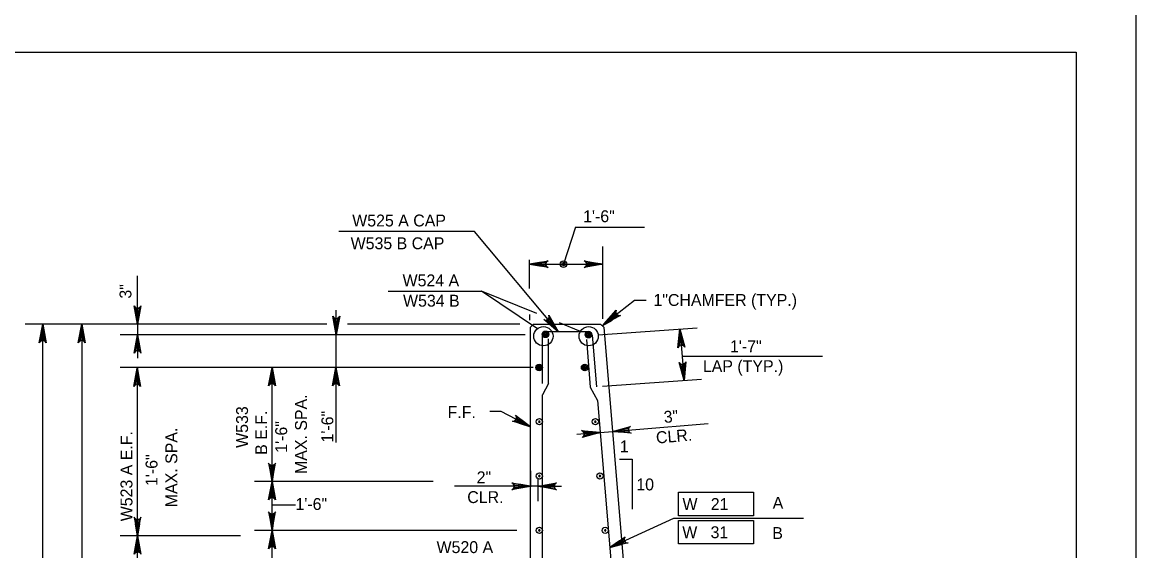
# Model space of a CAD drawing. Extents: x 638255 to 640306, y 296059 to 298435.
# Drawn here: x 639836.8 to 640117.5, y 297700.8 to 297834 of the extents above; entities that cross this region are included whole.
import ezdxf

# ---------------------------------------------------------------- set-up
doc = ezdxf.new("R2010")
doc.units = 0
for name, color, linetype in [('2', 7, 'Continuous'), ('3', 7, 'Continuous'), ('Level 3', 7, 'Continuous'), ('Level 4', 7, 'Continuous'), ('Level 6', 7, 'Continuous'), ('Level 9', 7, 'Continuous'), ('PLT-BNDY', 7, 'Continuous')]:
    doc.layers.add(name, color=color, linetype=linetype)

# ---------------------------------------------------------------- blocks, each defined once
blk = doc.blocks.new('B')
at = {"layer": '3'}
blk.add_circle((0, 0), 0.16, dxfattribs=at)
for start, end in [(0, 180), (180, 0)]:
    blk.add_arc((0, 0), 0.0391, start, end, dxfattribs=at)

msp = doc.modelspace()

# ---------------------------------------------------------------- linework, layer by layer
at = {"layer": '2'}
for p, q in [((639316.46, 297826.46), (640102.46, 297826.46)), ((640102.46, 297826.46), (640102.46, 297262.46))]:
    msp.add_line(p, q, dxfattribs=at)
at = {"layer": 'Level 3'}
for p, q in [((639976.26, 297782.34), (639973.23, 297773)), ((639976.26, 297782.34), (639993.65, 297782.34)), ((639966.64, 297756.74), (639952.56, 297766.23)), ((640003.08, 297749.78), (640038.49, 297749.78)), ((639899.73, 297712.35), (639905.68, 297712.35))]:
    msp.add_line(p, q, dxfattribs=at)
msp.add_lwpolyline([(640003.59, 297743.69), (640002.33, 297748.25), (640002.61, 297747.91), (640002.94, 297747.75), (640003.25, 297747.73), (640003.56, 297747.8), (640003.85, 297748.01), (640004.07, 297748.39), (640003.59, 297743.69), (640003.85, 297748.01), (640003.56, 297747.8), (640003.59, 297743.69), (640003.25, 297747.73), (640002.94, 297747.75), (640003.59, 297743.69), (640002.61, 297747.91)], dxfattribs=at)
for radius in [0.832, 0.416]:
    msp.add_circle((639973.23, 297773), radius, dxfattribs=at)
at = {"layer": 'Level 4'}
for p, q in [((639950.74, 297781.23), (639916.57, 297781.23)), ((639971.87, 297756.02), (639950.74, 297781.23)), ((639983.09, 297773.86), (639983.09, 297777.42)), ((639964.67, 297766.85), (639964.67, 297774.13)), ((639964.67, 297773), (639983.1, 297773)), ((639983.09, 297759.23), (639983.09, 297773.86)), ((639983.1, 297773), (639983.1, 297773)), ((639865.83, 297757.84), (639865.83, 297770.06)), ((639928.97, 297766.23), (639952.56, 297766.23)), ((639966.48, 297760.56), (639952.56, 297766.23)), ((639865.83, 297760.79), (639865.83, 297763.74)), ((639915.92, 297728.04), (639915.92, 297761.4)), ((639964.67, 297762.44), (639964.67, 297762.44)), ((639983.41, 297757.85), (639991.07, 297763.91)), ((639991.07, 297763.91), (639994.01, 297763.91)), ((639964.67, 297760.28), (639964.67, 297758.88)), ((639860.7, 297757.84), (639837.53, 297757.84)), ((639841.95, 297596.43), (639841.95, 297757.84)), ((639913.57, 297757.84), (639847.33, 297757.84)), ((639851.75, 297757.84), (639851.75, 297689.33)), ((639851.75, 297757.84), (639851.75, 297757.84)), ((639912.25, 297757.84), (639861.41, 297757.84)), ((639865.83, 297757.84), (639865.83, 297749.34)), ((639927.1, 297757.84), (639918.79, 297757.84)), ((639962.16, 297757.84), (639919.57, 297757.84)), ((639977.48, 297756.07), (639972.23, 297758.21)), ((639981.95, 297755.21), (640006.92, 297756.97)), ((640002.51, 297756.66), (640003.59, 297743.69)), ((639963.56, 297755.23), (639861.41, 297755.23)), ((639897.29, 297746.96), (639861.41, 297746.96)), ((639865.83, 297704.55), (639865.83, 297746.96)), ((639901.08, 297746.96), (639897.29, 297746.96)), ((639901.18, 297746.96), (639897.39, 297746.96)), ((639899.73, 297718.23), (639899.73, 297746.96)), ((639965.53, 297746.96), (639901.18, 297746.96)), ((639965.53, 297746.96), (639910.98, 297746.96)), ((639983.03, 297742.24), (640008, 297744)), ((639957.52, 297735.84), (639954.66, 297735.84)), ((639964.85, 297732.04), (639957.52, 297735.84)), ((639982.46, 297730.6), (639976.59, 297730.11)), ((639982.46, 297730.6), (639985.52, 297730.86)), ((639985.52, 297730.85), (639991.4, 297731.34)), ((639991.4, 297731.34), (640009.65, 297732.86)), ((639964.85, 297718.28), (639964.85, 297721.22)), ((639964.85, 297720.9), (639964.85, 297716.91)), ((639911.1, 297718.23), (639895.31, 297718.23)), ((639940.36, 297718.23), (639911.1, 297718.23)), ((639958.96, 297717.03), (639945.72, 297717.03)), ((639964.85, 297717.03), (639958.96, 297717.03)), ((639967.14, 297717.03), (639964.85, 297717.03)), ((639966.81, 297713.23), (639966.81, 297719.03)), ((639966.81, 297717.03), (639972.7, 297717.03)), ((639899.73, 297708.87), (639899.73, 297715.28)), ((640002.19, 297715.51), (640021.1, 297715.51)), ((640002.19, 297709.61), (640002.19, 297715.51)), ((640021.1, 297715.51), (640021.1, 297709.61)), ((639984.88, 297701.59), (640001.02, 297708.99)), ((640001.02, 297708.99), (640033.74, 297708.99)), ((640021.1, 297709.61), (640002.19, 297709.61)), ((640002.19, 297708.41), (640021.1, 297708.41)), ((640002.19, 297702.51), (640002.19, 297708.41)), ((640021.1, 297708.41), (640021.1, 297702.51)), ((639961.47, 297705.92), (639895.31, 297705.92)), ((639899.73, 297623.85), (639899.73, 297705.92)), ((639865.24, 297704.55), (639861.41, 297704.55)), ((639891.79, 297704.55), (639861.41, 297704.55)), ((640021.1, 297702.51), (640002.19, 297702.51)), ((639865.83, 297695.19), (639865.83, 297701.61))]:
    msp.add_line(p, q, dxfattribs=at)
for points in [[(639964.67, 297773), (639969.32, 297773.87), (639968.96, 297773.62), (639968.78, 297773.31), (639968.72, 297773), (639968.78, 297772.69), (639968.96, 297772.38), (639969.32, 297772.13), (639964.67, 297773), (639968.96, 297772.38), (639968.78, 297772.69), (639964.67, 297773), (639968.72, 297773), (639968.78, 297773.31), (639964.67, 297773), (639968.96, 297773.62)], [(639983.1, 297773), (639978.44, 297772.13), (639978.8, 297772.38), (639978.99, 297772.69), (639979.04, 297773), (639978.99, 297773.31), (639978.8, 297773.62), (639978.44, 297773.87), (639983.1, 297773), (639978.8, 297773.62), (639978.99, 297773.31), (639983.1, 297773), (639979.04, 297773), (639978.99, 297772.69), (639983.1, 297773), (639978.8, 297772.38)], [(639865.83, 297757.84), (639864.96, 297762.5), (639865.2, 297762.14), (639865.52, 297761.95), (639865.83, 297761.9), (639866.14, 297761.95), (639866.45, 297762.14), (639866.7, 297762.5), (639865.83, 297757.84), (639866.45, 297762.14), (639866.14, 297761.95), (639865.83, 297757.84), (639865.83, 297761.9), (639865.52, 297761.95), (639865.83, 297757.84), (639865.2, 297762.14)], [(639983.41, 297757.85), (639986.51, 297761.42), (639986.39, 297761), (639986.44, 297760.64), (639986.59, 297760.36), (639986.82, 297760.15), (639987.16, 297760.02), (639987.6, 297760.05), (639983.41, 297757.85), (639987.16, 297760.02), (639986.82, 297760.15), (639983.41, 297757.85), (639986.59, 297760.36), (639986.44, 297760.64), (639983.41, 297757.85), (639986.39, 297761)], [(639915.92, 297755.23), (639915.05, 297759.88), (639915.29, 297759.53), (639915.61, 297759.34), (639915.92, 297759.29), (639916.23, 297759.34), (639916.54, 297759.53), (639916.79, 297759.88), (639915.92, 297755.23), (639916.54, 297759.53), (639916.23, 297759.34), (639915.92, 297755.23), (639915.92, 297759.29), (639915.61, 297759.34), (639915.92, 297755.23), (639915.29, 297759.53)], [(639971.87, 297756.02), (639968.22, 297759.03), (639968.64, 297758.91), (639969, 297758.97), (639969.27, 297759.13), (639969.47, 297759.37), (639969.59, 297759.71), (639969.55, 297760.15), (639971.87, 297756.02), (639969.59, 297759.71), (639969.47, 297759.37), (639971.87, 297756.02), (639969.27, 297759.13), (639969, 297758.97), (639971.87, 297756.02), (639968.64, 297758.91)], [(639841.95, 297757.84), (639842.82, 297753.19), (639842.57, 297753.55), (639842.26, 297753.73), (639841.95, 297753.79), (639841.63, 297753.73), (639841.32, 297753.55), (639841.07, 297753.19), (639841.95, 297757.84), (639841.32, 297753.55), (639841.63, 297753.73), (639841.95, 297757.84), (639841.95, 297753.79), (639842.26, 297753.73), (639841.95, 297757.84), (639842.57, 297753.55)], [(639851.75, 297757.84), (639852.62, 297753.19), (639852.37, 297753.55), (639852.06, 297753.73), (639851.75, 297753.79), (639851.44, 297753.73), (639851.13, 297753.55), (639850.88, 297753.19), (639851.75, 297757.84), (639851.13, 297753.55), (639851.44, 297753.73), (639851.75, 297757.84), (639851.75, 297753.79), (639852.06, 297753.73), (639851.75, 297757.84), (639852.37, 297753.55)], [(640002.51, 297756.66), (640003.76, 297752.09), (640003.49, 297752.43), (640003.16, 297752.59), (640002.85, 297752.62), (640002.54, 297752.54), (640002.24, 297752.33), (640002.02, 297751.95), (640002.51, 297756.66), (640002.24, 297752.33), (640002.54, 297752.54), (640002.51, 297756.66), (640002.85, 297752.62), (640003.16, 297752.59), (640002.51, 297756.66), (640003.49, 297752.43)], [(639865.83, 297755.23), (639866.7, 297750.58), (639866.45, 297750.94), (639866.14, 297751.12), (639865.83, 297751.18), (639865.52, 297751.12), (639865.2, 297750.94), (639864.96, 297750.58), (639865.83, 297755.23), (639865.2, 297750.94), (639865.52, 297751.12), (639865.83, 297755.23), (639865.83, 297751.18), (639866.14, 297751.12), (639865.83, 297755.23), (639866.45, 297750.94)], [(639865.74, 297746.8), (639866.61, 297742.15), (639866.36, 297742.51), (639866.05, 297742.69), (639865.74, 297742.75), (639865.43, 297742.69), (639865.11, 297742.51), (639864.87, 297742.15), (639865.74, 297746.8), (639865.11, 297742.51), (639865.43, 297742.69), (639865.74, 297746.8), (639865.74, 297742.75), (639866.05, 297742.69), (639865.74, 297746.8), (639866.36, 297742.51)], [(639899.73, 297746.96), (639900.6, 297742.3), (639900.35, 297742.66), (639900.04, 297742.85), (639899.73, 297742.9), (639899.42, 297742.85), (639899.11, 297742.66), (639898.86, 297742.3), (639899.73, 297746.96), (639899.11, 297742.66), (639899.42, 297742.85), (639899.73, 297746.96), (639899.73, 297742.9), (639900.04, 297742.85), (639899.73, 297746.96), (639900.35, 297742.66)], [(639915.85, 297746.96), (639916.72, 297742.3), (639916.48, 297742.66), (639916.17, 297742.85), (639915.85, 297742.9), (639915.54, 297742.85), (639915.23, 297742.66), (639914.98, 297742.3), (639915.85, 297746.96), (639915.23, 297742.66), (639915.54, 297742.85), (639915.85, 297746.96), (639915.85, 297742.9), (639916.17, 297742.85), (639915.85, 297746.96), (639916.48, 297742.66)], [(639964.85, 297732.04), (639960.32, 297733.4), (639960.75, 297733.46), (639961.06, 297733.65), (639961.25, 297733.9), (639961.35, 297734.2), (639961.33, 297734.57), (639961.13, 297734.95), (639964.85, 297732.04), (639961.33, 297734.57), (639961.35, 297734.2), (639964.85, 297732.04), (639961.25, 297733.9), (639961.06, 297733.65), (639964.85, 297732.04), (639960.75, 297733.46)], [(639982.46, 297730.6), (639977.9, 297729.34), (639978.24, 297729.62), (639978.39, 297729.95), (639978.42, 297730.26), (639978.34, 297730.57), (639978.13, 297730.87), (639977.76, 297731.08), (639982.46, 297730.6), (639978.13, 297730.87), (639978.34, 297730.57), (639982.46, 297730.6), (639978.42, 297730.26), (639978.39, 297729.95), (639982.46, 297730.6), (639978.24, 297729.62)], [(639985.52, 297730.85), (639990.08, 297732.11), (639989.75, 297731.83), (639989.59, 297731.51), (639989.56, 297731.19), (639989.64, 297730.88), (639989.85, 297730.59), (639990.23, 297730.37), (639985.52, 297730.85), (639989.85, 297730.59), (639989.64, 297730.88), (639985.52, 297730.85), (639989.56, 297731.19), (639989.59, 297731.51), (639985.52, 297730.85), (639989.75, 297731.83)], [(639899.73, 297718.23), (639900.6, 297722.88), (639900.35, 297722.52), (639900.04, 297722.34), (639899.73, 297722.28), (639899.42, 297722.34), (639899.11, 297722.52), (639898.86, 297722.88), (639899.73, 297718.23), (639899.11, 297722.52), (639899.42, 297722.34), (639899.73, 297718.23), (639899.73, 297722.28), (639900.04, 297722.34), (639899.73, 297718.23), (639900.35, 297722.52)], [(639899.73, 297718.23), (639900.6, 297713.58), (639900.35, 297713.94), (639900.04, 297714.12), (639899.73, 297714.17), (639899.42, 297714.12), (639899.11, 297713.94), (639898.86, 297713.58), (639899.73, 297718.23), (639899.11, 297713.94), (639899.42, 297714.12), (639899.73, 297718.23), (639899.73, 297714.17), (639900.04, 297714.12), (639899.73, 297718.23), (639900.35, 297713.94)], [(639964.85, 297717.03), (639960.2, 297716.16), (639960.56, 297716.41), (639960.74, 297716.72), (639960.8, 297717.03), (639960.74, 297717.34), (639960.56, 297717.66), (639960.2, 297717.9), (639964.85, 297717.03), (639960.56, 297717.66), (639960.74, 297717.34), (639964.85, 297717.03), (639960.8, 297717.03), (639960.74, 297716.72), (639964.85, 297717.03), (639960.56, 297716.41)], [(639966.81, 297717.03), (639971.46, 297717.9), (639971.1, 297717.66), (639970.92, 297717.34), (639970.86, 297717.03), (639970.92, 297716.72), (639971.1, 297716.41), (639971.46, 297716.16), (639966.81, 297717.03), (639971.1, 297716.41), (639970.92, 297716.72), (639966.81, 297717.03), (639970.86, 297717.03), (639970.92, 297717.34), (639966.81, 297717.03), (639971.1, 297717.66)], [(639865.83, 297704.55), (639866.7, 297709.2), (639866.45, 297708.85), (639866.14, 297708.66), (639865.83, 297708.61), (639865.52, 297708.66), (639865.2, 297708.85), (639864.96, 297709.2), (639865.83, 297704.55), (639865.2, 297708.85), (639865.52, 297708.66), (639865.83, 297704.55), (639865.83, 297708.61), (639866.14, 297708.66), (639865.83, 297704.55), (639866.45, 297708.85)], [(639899.73, 297705.92), (639900.6, 297710.57), (639900.35, 297710.21), (639900.04, 297710.03), (639899.73, 297709.97), (639899.42, 297710.03), (639899.11, 297710.21), (639898.86, 297710.57), (639899.73, 297705.92), (639899.11, 297710.21), (639899.42, 297710.03), (639899.73, 297705.92), (639899.73, 297709.97), (639900.04, 297710.03), (639899.73, 297705.92), (639900.35, 297710.21)], [(639899.73, 297705.92), (639900.6, 297701.27), (639900.35, 297701.63), (639900.04, 297701.81), (639899.73, 297701.87), (639899.42, 297701.81), (639899.11, 297701.63), (639898.86, 297701.27), (639899.73, 297705.92), (639899.11, 297701.63), (639899.42, 297701.81), (639899.73, 297705.92), (639899.73, 297701.87), (639900.04, 297701.81), (639899.73, 297705.92), (639900.35, 297701.63)], [(639865.83, 297704.55), (639866.7, 297699.9), (639866.45, 297700.26), (639866.14, 297700.44), (639865.83, 297700.5), (639865.52, 297700.44), (639865.2, 297700.26), (639864.96, 297699.9), (639865.83, 297704.55), (639865.2, 297700.26), (639865.52, 297700.44), (639865.83, 297704.55), (639865.83, 297700.5), (639866.14, 297700.44), (639865.83, 297704.55), (639866.45, 297700.26)], [(639984.88, 297701.59), (639988.74, 297704.32), (639988.52, 297703.94), (639988.48, 297703.58), (639988.56, 297703.28), (639988.74, 297703.01), (639989.04, 297702.81), (639989.47, 297702.73), (639984.88, 297701.59), (639989.04, 297702.81), (639988.74, 297703.01), (639984.88, 297701.59), (639988.56, 297703.28), (639988.48, 297703.58), (639984.88, 297701.59), (639988.52, 297703.94)]]:
    msp.add_lwpolyline(points, dxfattribs=at)
for points in [[(639967.62, 297772.51), (639967.62, 297773.49), (639964.67, 297773)], [(639980.15, 297772.51), (639980.15, 297773.49), (639983.1, 297773)], [(639865.34, 297760.79), (639866.32, 297760.79), (639865.83, 297757.84)], [(639970.36, 297758.59), (639969.61, 297757.96), (639971.88, 297756.02)], [(639985.54, 297758.91), (639984.93, 297759.68), (639982.92, 297757.46)], [(639841.46, 297754.9), (639842.44, 297754.9), (639841.95, 297757.84)], [(639852.24, 297754.9), (639851.26, 297754.9), (639851.75, 297757.84)], [(639915.43, 297758.18), (639916.41, 297758.18), (639915.92, 297755.23)], [(640003.25, 297753.7), (640002.27, 297753.62), (640002.51, 297756.6)], [(639865.34, 297752.29), (639866.32, 297752.29), (639865.83, 297755.23)], [(639865.34, 297744.01), (639866.32, 297744.01), (639865.83, 297746.96)], [(639899.24, 297744.01), (639900.22, 297744.01), (639899.73, 297746.96)], [(639915.43, 297744.01), (639916.41, 297744.01), (639915.92, 297746.96)], [(640003.84, 297746.61), (640002.86, 297746.52), (640003.59, 297743.63)], [(639962.46, 297733.83), (639962.01, 297732.96), (639964.85, 297732.03)], [(639979.49, 297730.85), (639979.57, 297729.87), (639982.46, 297730.6)], [(639988.42, 297731.59), (639988.5, 297730.61), (639985.52, 297730.86)], [(639899.24, 297721.18), (639900.22, 297721.18), (639899.73, 297718.23)], [(639899.24, 297715.28), (639900.22, 297715.28), (639899.73, 297718.23)], [(639961.91, 297717.52), (639961.91, 297716.54), (639964.85, 297717.03)], [(639969.76, 297717.52), (639969.76, 297716.54), (639966.81, 297717.03)], [(639899.24, 297708.87), (639900.22, 297708.87), (639899.73, 297705.92)], [(639865.34, 297707.5), (639866.32, 297707.5), (639865.83, 297704.55)], [(639899.24, 297702.97), (639900.22, 297702.97), (639899.73, 297705.92)], [(639865.34, 297701.61), (639866.32, 297701.61), (639865.83, 297704.55)], [(639987.76, 297702.37), (639987.35, 297703.26), (639984.88, 297701.59)]]:
    msp.add_lwpolyline(points, close=True, dxfattribs=at)
for centre in [(639968.14, 297754.84), (639979.56, 297754.84)]:
    msp.add_circle(centre, 2.42, dxfattribs=at)
at = {"layer": 'Level 6'}
for p, q in [((639968.94, 297756.02), (639979.4, 297756.02)), ((639967.91, 297742.95), (639967.91, 297755)), ((639969.45, 297742.95), (639969.45, 297754.18)), ((639978.97, 297753.99), (639979.97, 297741.98)), ((639980.42, 297755.08), (639981.5, 297742.11)), ((639969.45, 297742.95), (639967.91, 297740.11)), ((639979.97, 297741.98), (639981.79, 297738.62)), ((639967.91, 297666.09), (639967.91, 297740.11)), ((639981.79, 297738.62), (639986.12, 297686.75))]:
    msp.add_line(p, q, dxfattribs=at)
for centre, radius in [((639968.69, 297755.32), 0.832), ((639968.69, 297755.32), 0.624), ((639968.69, 297755.32), 0.416), ((639979.54, 297755.23), 0.832), ((639979.54, 297755.23), 0.624), ((639979.54, 297755.23), 0.416), ((639968.69, 297755.32), 0.208), ((639979.54, 297755.23), 0.208), ((639967.07, 297746.96), 0.832), ((639967.07, 297746.96), 0.624), ((639967.07, 297746.96), 0.416), ((639978.55, 297746.96), 0.832), ((639978.55, 297746.96), 0.624), ((639978.55, 297746.96), 0.416), ((639967.07, 297746.96), 0.208), ((639978.55, 297746.96), 0.208)]:
    msp.add_circle(centre, radius, dxfattribs=at)
for centre, start, end in [((639968.93, 297755), 90, 180), ((639979.4, 297755), 4.7636, 90)]:
    msp.add_arc(centre, 1.02, start, end, dxfattribs=at)
at = {"layer": 'Level 9'}
for p, q in [((639965.62, 297757.85), (639964.85, 297757.08)), ((639964.85, 297621.09), (639964.85, 297757.08)), ((639965.62, 297757.85), (639982.51, 297757.85)), ((639982.51, 297757.85), (639983.34, 297757.08)), ((639983.34, 297757.08), (639994.67, 297621.09))]:
    msp.add_line(p, q, dxfattribs=at)
msp.add_lwpolyline([(639987.33, 297723.84), (639990.55, 297723.84), (639990.55, 297711.28)], dxfattribs=at)
at = {"layer": 'PLT-BNDY'}
msp.add_lwpolyline([(639276.46, 297841.46), (640117.46, 297841.46), (640117.46, 297247.46), (639276.46, 297247.46)], close=True, dxfattribs=at)

# ---------------------------------------------------------------- block references
at = {"layer": 'Level 3', "xscale": 4.911876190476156, "yscale": 4.911876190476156, "rotation": 90}
for p in [(639967.13, 297733.28), (639981.25, 297733.28), (639967.13, 297719.6), (639982.4, 297719.6), (639967.13, 297705.92), (639983.72, 297705.92)]:
    msp.add_blockref('B', p, dxfattribs=at)

# ---------------------------------------------------------------- texts
at = {"layer": 'Level 3'}
for s, height, p in [('1\'-6"', 3, (639978.15, 297783.57)), ('1"CHAMFER (TYP.)', 3.0001, (639995.88, 297762.47)), ('1\'-7"', 3, (640015.18, 297750.8)), ('LAP (TYP.)', 3, (640008.34, 297745.8)), ('2"', 3, (639951.32, 297717.78)), ('CLR.', 3, (639948.95, 297712.79))]:
    msp.add_text(s, height=height, dxfattribs=at).set_placement(p)
for s, rotation, p in [('3"', 90, (639864.29, 297764.31)), ('3"', 4.7636, (639998.6, 297732.96)), ('CLR.', 4.7636, (639996.65, 297727.78))]:
    msp.add_text(s, height=3, rotation=rotation, dxfattribs=at).set_placement(p)
at = {"layer": 'Level 4'}
for s, p in [('W525 A CAP', (639919.95, 297782.5)), ('W535 B CAP', (639919.55, 297776.76)), ('W524 A', (639932.64, 297767.41)), ('W534 B', (639932.76, 297762.29)), ('F.F.', (639943.99, 297734.22)), ('1', (639987.4, 297725.57)), ('10', (639991.56, 297715.99)), ('1\'-6"', (639905.64, 297711.05)), ('W   21', (640003.2, 297711.04)), ('A', (640025.94, 297711.36)), ('W   31', (640003.15, 297703.94)), ('B', (640025.84, 297703.74)), ('W520 A', (639941.21, 297700.19))]:
    msp.add_text(s, height=3, dxfattribs=at).set_placement(p)
for s, height, p in [('MAX. SPA.', 3, (639908.54, 297720.11)), ('W533', 3, (639893.68, 297726.7)), ('B E.F.', 3, (639898.5, 297724.95)), ('1\'-6"', 3, (639903.54, 297725.46)), ('1\'-6"', 3, (639915.18, 297728.05)), ('W523 A E.F.', 3.0001, (639864.54, 297708.2)), ('MAX. SPA.', 3, (639875.86, 297711.74)), ('1\'-6"', 3, (639870.86, 297717.09))]:
    msp.add_text(s, height=height, rotation=90, dxfattribs=at).set_placement(p)

doc.saveas('drawing.dxf')
